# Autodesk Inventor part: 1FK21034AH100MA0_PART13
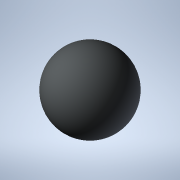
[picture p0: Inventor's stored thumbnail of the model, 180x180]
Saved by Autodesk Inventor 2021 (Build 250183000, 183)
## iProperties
Created: 2025-04
Part Number: 1FK21034AH100MA0_PART13
Material: Generic
Catalog Web Link: www.3dfindit.com
Description: -Servo synchronous motor
Document SubType Name: Modeling
Designer: psAdmin
Mass: 0.113097 g
Surface Area: 1.13097 cm^2
Volume: 0.113097 cm^3
Density: 1 g/cm^3
Appearance: PSOLRGB-212-217-219
Category: PARTsolutions
Title: 1FK21034AH100MA0_PART13
Author: Cadenas PARTsolutions
Comments: Servo synchronous motor
Sending System: PARTsolutions
Preprocessor: ST-DEVELOPER v19.3
PSOL_IDENT_0: {$CADENAS_DATA/23d-libs/siemens_ag/_cat_/39/97/1fk21034ah100ma0.prj},216 {VTYP=3D},{NB=1FK21034AH100
PSOL_IDENT_1: MA0_PART13},{LINA=1FK21034AH100MA0_PART13},{NN=1FK21034AH100MA0_PART13},{NOPRJ=TRUE},{DATE=19.08.202
PSOL_IDENT_2: 5 14:00:33},{GEOMDATE=30.07.2025 02:02:21},{VERSION=},{LINEID=10},{WBVAR=},{WBNUMERIC=}  {NB=1FK2103
PSOL_IDENT_3: 4AH100MA0_PART13},{LINA=1FK21034AH100MA0_PART13},{KT=DUMMY},{PREVIEW=../../../_pool_/d3/78/p_d211_xx
PSOL_IDENT_4: _00934j.png},{DESCSHORT=SIMOTICS S-1FK2 HD, SINAMICS S210 3AC 400V-480V, 1.01 Nm, 4500 rpm},{DESCLON
PSOL_IDENT_5: G=SIMOTICS S-1FK2 HD servo motor M0=1.27 Nm; PN = 0.48 kW at nN=4500 rpm (380-480 V); PN = 0.3 kW at
PSOL_IDENT_6: nN=2500 rpm (200-240 V); with holding brake; degree of protection IP64; cylindrical shaft D14 x 30
PSOL_IDENT_7: mm; absolute encoder 22-bit + 12-bit multiturn (encoder AM22DQC); with OCC interface; plug size M17,
PSOL_IDENT_8: rotatable; SIMOTICS S-1FK2 servomotorfor a wide range of uses in industrial environments. SIMOTICS
PSOL_IDENT_9: S‑1FK2 servomotors are compact synchronous motors with a high dynamic performance that set themselve
PSOL_IDENT_10: s apart as a result of their high power density, degree of protection and overload capability. The m
PSOL_IDENT_11: otors are available in two variants: as High Dynamic variant (highest dynamic performance as a resul
PSOL_IDENT_12: t of the low intrinsic moment of inertia for applications demanding a high dynamic performance with
PSOL_IDENT_13: low moved masses) - and as Compact variant (precise and stable closed-loop control for medium up to
PSOL_IDENT_14: large moved masses as a result of a medium intrinsic moment of inertia). SIMOTICSS‑1FK2 servomotors
PSOL_IDENT_15: fully exploit their strengths in a system with the SINAMICSS210 frequency converter and simple conne
PSOL_IDENT_16: ction using the one cable connection (OCC). Advantages include the short control and positioning tim
PSOL_IDENT_17: es, fast and precise correction of disturbing quantities as well as stable control with a high dynam
PSOL_IDENT_18: ic performance. The servo motors can be configured to address a wide range of requirements. For exam
PSOL_IDENT_19: ple with and without holding brake, IP64 or IP65 degree of protection, singleturn or multiturn absol
PSOL_IDENT_20: ute encoders - to name just a few. Further, the servomotors are available in different shaft heights
PSOL_IDENT_21: extending from 20 to 100. A shaft sealing ring is available to achieve an IP65 degree of protection
PSOL_IDENT_22: and for subsequent mounting at the motor or as spare part. SIMOTICS - the optimum motor for each an
PSOL_IDENT_23: d every motion control application.},{INTNO=195125454019},{SUPPLIERALTNO=1FK2103-4AH10-0MA0},{MANUID=
PSOL_IDENT_24: 1FK21034AH100MA0},{MANUNAME=Siemens},{MANUTYPEDESC=SYNCHRONOUS MOTOR 1FK2 HD 1,27 NM},{AAU732=SIMOTI
PSOL_IDENT_25: CS},{AAO057=S-1FK2},{AAU734=SIMOTICS S-1FK2 HD servo motor M0=1.27 Nm; PN = 0.48 kW at nN=4500 rpm (
PSOL_IDENT_26: 380-480 V); PN = 0.3 kW at nN=2500 rpm (200-240 V); with holding brake; degree of protection IP64; c
PSOL_IDENT_27: ylindrical shaft D14 x 30 mm; absolute encoder 22-bit + 12-bit multiturn (encoder AM22DQC); with OCC
PSOL_IDENT_28: interface; plug size M17, rotatable;},{AAW338=SYNCHRONOUS MOTOR 1FK2 HD 1,27 NM},{AAO742=SIMOTICS},
PSOL_IDENT_29: {AAO663=4034106444921},{NOCUPEROU=1},{PRICEQUANTITY=1},{QUANTITYMIN=1},{QUANTITYINT=1},{CTN=85015100
PSOL_IDENT_30: },{COO=RO},{AAO676=1FK2103-4AH10-0MA0},{AAO677=Siemens AG},{ORDERUNIT=C62},{CONTENTUNIT=C62}
NB: 1FK21034AH100MA0_PART13
NT: Servo synchronous motor
NBSYN: $MANUID._PART13
LINA: 1FK21034AH100MA0_PART13
CATALOG: SIEMENS
PREVIEW: ../../../_pool_/d3/78/p_d211_xx_00934j.png
DESCSHORT: SIMOTICS S-1FK2 HD, SINAMICS S210 3AC 400V-480V, 1.01 Nm, 4500 rpm
DESCLONG: SIMOTICS S-1FK2 HD servo motor M0=1.27 Nm; PN = 0.48 kW at nN=4500 rpm (380-480 V); PN = 0.3 kW at nN=2500 rpm (200-240 V); with holding brake; degree of protec
INTNO: 195125454019
SUPPLIERALTNO: 1FK2103-4AH10-0MA0
MANUID: 1FK21034AH100MA0
MANUNAME: Siemens
MANUTYPEDESC: SYNCHRONOUS MOTOR 1FK2 HD 1,27 NM
AAU732: SIMOTICS
AAO057: S-1FK2
AAU734: SIMOTICS S-1FK2 HD servo motor M0=1.27 Nm; PN = 0.48 kW at nN=4500 rpm (380-480 V); PN = 0.3 kW at nN=2500 rpm (200-240 V); with holding brake; degree of protec
AAW338: SYNCHRONOUS MOTOR 1FK2 HD 1,27 NM
AAO742: SIMOTICS
AAO663: 4034106444921.0
NOCUPEROU: 1
PRICEQUANTITY: 1
QUANTITYMIN: 1
QUANTITYINT: 1
CTN: 85015100
COO: RO
ARTICLENO: 1FK21034AH100MA0_PART13
BOMINFO: 1FK21034AH100MA0_PART13
CREATOR: CADENAS GmbH
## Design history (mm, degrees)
feature "2025_04_17_15_09_00_0361"
body "Solid1"
